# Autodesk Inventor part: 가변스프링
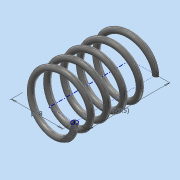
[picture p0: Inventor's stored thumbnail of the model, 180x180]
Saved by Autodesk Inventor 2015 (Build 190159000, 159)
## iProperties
Created: 2017-12
Part Number: 가변스프링
Material: 스테인레스 스틸
Document SubType Name: Modeling
Designer: SCD-A03
Density: 8 g/cm^3
Appearance: 반연마
Mass: 7.00032 g
Surface Area: 17.7539 cm^2
Volume: 0.87504 cm^3
Author: SCD-A03
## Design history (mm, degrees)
sketch "스케치1"
  geometry: L1 (0, 0)-(9, 0); L2 (9, 0)-(9, 28.5); L3 (9, 28.5)-(0, 28.5); L4 (0, 28.5)-(0, 0); C1 r 1 at (9, 0)
  constraints: 8 end point, 2 parallel, 1 centre point, 1 coincident, 1 horizontal, 1 perpendicular
  dimensions: "d1" = 2 diameter of C1; "d3" = 18 diameter of L2 L4; "d5" = 28.5 distance of L1.end L2.end (derived)
feature "코일1" pitch "d6" = 10; turns "d8" = 5; dims "d7" = 28.5 (= d5), "d9" = 0, angle "d10" = 90 deg, angle "d11" = 90 deg, "d12" = 0, "d13" = 0
sketch "스케치2"
  geometry: L1 (-10, 0)-(-8, 0) reference; 1 further point
  constraints: 1 horizontal alignment
extrude "돌출1" cut sketch "스케치2" stored distance "d14" = 10; taper "d15" = 0 deg
node "작업 평면1"
sketch "스케치3"
  geometry: L1 (1, 0)-(-1, 0) reference; 1 further point
  constraints: 1 horizontal alignment
extrude "돌출2" cut sketch "스케치3" stored distance "d17" = 10; taper "d18" = 0 deg
node "솔리드1"
node "절단 모서리 투영1"
node "절단 모서리 투영2"
other parameters: "d16" = 90 deg
